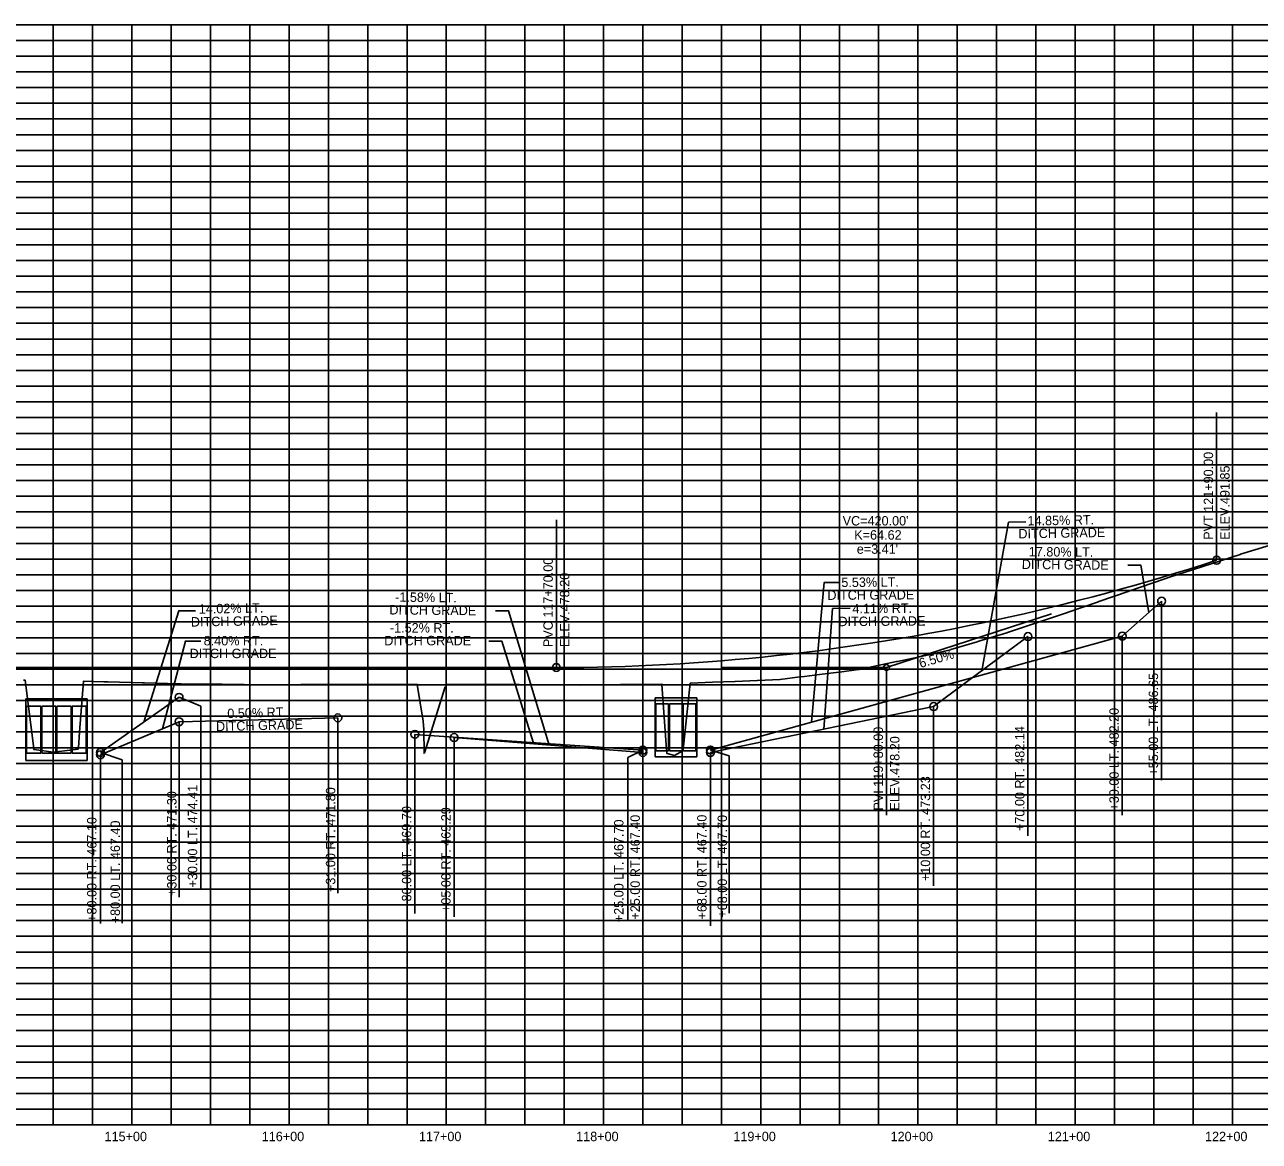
# Model space of a CAD drawing. Extents: x 1054002 to 1056762, y 395173 to 397393.
# Drawn here: x 1055464 to 1056249, y 396673 to 397383 of the extents above; entities that cross this region are included whole.
import ezdxf

# ---------------------------------------------------------------- set-up
doc = ezdxf.new("R2010")
doc.units = 0
for name, color, linetype in [('Level 8', 7, 'Continuous'), ('R_Axis_Annotation', 7, 'Continuous'), ('R_Drainage', 7, 'Continuous'), ('R_Exist Surface', 7, 'Continuous'), ('R_Grid', 7, 'Continuous'), ('R_Grid_Minor', 7, 'Continuous'), ('R_Vert Alg', 7, 'Continuous'), ('R_Vert Alg Annot', 7, 'Continuous')]:
    doc.layers.add(name, color=color, linetype=linetype)

msp = doc.modelspace()

# ---------------------------------------------------------------- linework, layer by layer
at = {"layer": 'Level 8'}
msp.add_line((1055912.29, 396918.32), (1055900.3, 396921.92), dxfattribs=at)
at = {"layer": 'R_Drainage'}
for p, q in [((1055464.75, 396954.45), (1055503.83, 396954.45)), ((1055464.75, 396954.45), (1055464.75, 396915.28)), ((1055503.83, 396954.45), (1055503.83, 396915.28)), ((1055865.04, 396955.06), (1055891.54, 396955.06)), ((1055865.04, 396955.06), (1055865.04, 396917.56)), ((1055891.54, 396955.06), (1055891.54, 396917.56)), ((1055465.29, 396949.86), (1055465.29, 396919.86)), ((1055465.29, 396949.86), (1055474.29, 396949.86)), ((1055474.29, 396949.86), (1055474.29, 396919.86)), ((1055474.96, 396949.86), (1055474.96, 396919.86)), ((1055474.96, 396949.86), (1055483.96, 396949.86)), ((1055483.96, 396949.86), (1055483.96, 396919.86)), ((1055484.63, 396949.86), (1055484.63, 396919.86)), ((1055484.63, 396949.86), (1055493.63, 396949.86)), ((1055493.63, 396949.86), (1055493.63, 396919.86)), ((1055494.29, 396949.86), (1055494.29, 396919.86)), ((1055494.29, 396949.86), (1055503.29, 396949.86)), ((1055503.29, 396949.86), (1055503.29, 396919.86)), ((1055865.63, 396951.31), (1055865.63, 396921.31)), ((1055865.63, 396951.31), (1055873.63, 396951.31)), ((1055873.63, 396951.31), (1055873.63, 396921.31)), ((1055874.29, 396951.31), (1055874.29, 396921.31)), ((1055874.29, 396951.31), (1055882.29, 396951.31)), ((1055882.29, 396951.31), (1055882.29, 396921.31)), ((1055882.96, 396951.31), (1055882.96, 396921.31)), ((1055882.96, 396951.31), (1055890.96, 396951.31)), ((1055890.96, 396951.31), (1055890.96, 396921.31)), ((1055865.63, 396921.31), (1055873.63, 396921.31)), ((1055874.29, 396921.31), (1055882.29, 396921.31)), ((1055882.96, 396921.31), (1055890.96, 396921.31)), ((1055464.75, 396915.28), (1055503.83, 396915.28)), ((1055465.29, 396919.86), (1055474.29, 396919.86)), ((1055474.96, 396919.86), (1055483.96, 396919.86)), ((1055483.96, 396919.86), (1055484.63, 396919.86)), ((1055484.63, 396919.86), (1055493.63, 396919.86)), ((1055494.29, 396919.86), (1055503.29, 396919.86)), ((1055865.04, 396917.56), (1055891.54, 396917.56))]:
    msp.add_line(p, q, dxfattribs=at)
at = {"layer": 'R_Exist Surface'}
msp.add_lwpolyline([(1055463.37, 396966.38), (1055464.37, 396966.39), (1055469.93, 396922.98), (1055469.96, 396922.21), (1055470.12, 396922.22), (1055482.15, 396920.53), (1055482.33, 396920.5), (1055492.8, 396921.8), (1055498.03, 396922.41), (1055498.22, 396922.5), (1055498.32, 396923.55), (1055499.05, 396933.35), (1055501.45, 396965.66), (1055514.54, 396965.34), (1055515.84, 396965.29), (1055517.1, 396965.23), (1055539.07, 396964.7), (1055540.3, 396964.64), (1055562.31, 396964.11), (1055563.53, 396964.06), (1055575.9, 396963.93), (1055577.44, 396963.91), (1055589.82, 396963.78), (1055602.32, 396963.66), (1055603.66, 396963.64), (1055616.17, 396963.51), (1055639.65, 396963.57), (1055640.75, 396963.58), (1055664.42, 396963.64), (1055665.34, 396963.65), (1055688.18, 396963.66), (1055689.59, 396963.65), (1055711.98, 396963.66), (1055713.85, 396963.66), (1055717.47, 396940.23), (1055718.08, 396934.95), (1055718.17, 396919.92), (1055718.37, 396920.16), (1055731.64, 396962.03), (1055732.16, 396961.95), (1055732.26, 396963.75), (1055748.33, 396963.7), (1055748.98, 396963.7), (1055765.31, 396963.65), (1055765.65, 396963.65), (1055778.3, 396963.55), (1055778.72, 396963.55), (1055791.37, 396963.45), (1055804.07, 396963.35), (1055804.41, 396963.35), (1055817.1, 396963.25), (1055830.05, 396963.4), (1055830.19, 396963.4), (1055843.15, 396963.56), (1055843.29, 396963.56), (1055856.25, 396963.71), (1055856.38, 396963.71), (1055869.36, 396963.87), (1055869.47, 396963.87), (1055872.45, 396922.07), (1055872.52, 396919.78), (1055872.7, 396919.78), (1055877.36, 396918.43), (1055877.46, 396918.47), (1055882.74, 396921.44), (1055882.76, 396921.5), (1055882.85, 396922.36), (1055887.4, 396964.42), (1055887.53, 396964.43), (1055901.71, 396965.03), (1055915.82, 396965.62), (1055916.03, 396965.63), (1055930.11, 396966.23), (1055930.35, 396966.24), (1055944.41, 396966.83), (1055944.69, 396966.85), (1055957.09, 396968.41), (1055957.17, 396968.42), (1055960.04, 396968.79), (1055969.57, 396969.97), (1055969.71, 396969.99), (1055982.02, 396971.52), (1055982.33, 396971.57), (1055994.48, 396973.08), (1055994.97, 396973.16), (1056018.69, 396978.19), (1056019.33, 396978.33), (1056043.33, 396983.42), (1056043.69, 396983.5), (1056052.92, 396985.77), (1056052.96, 396985.78), (1056053.16, 396985.84), (1056069.91, 396990.86), (1056070.94, 396991.17), (1056070.95, 396991.17), (1056088.92, 396996.54), (1056089.17, 396996.62), (1056108.4, 397003.09), (1056127.47, 397009.5), (1056127.89, 397009.63), (1056146.54, 397016.1), (1056146.94, 397016.23), (1056147.33, 397016.37), (1056165.99, 397022.84), (1056166.51, 397023.01), (1056189.37, 397030.87), (1056191.58, 397031.59), (1056213.45, 397038.67), (1056237.15, 397046.33), (1056237.54, 397046.46), (1056246.6, 397049.21), (1056260.64, 397053.44)], dxfattribs=at)
at = {"layer": 'R_Grid'}
for p, q in [((1054032.29, 397383.41), (1056732.29, 397383.41)), ((1054032.29, 397383.41), (1056732.29, 397383.41)), ((1055532.29, 396683.41), (1055532.29, 397383.41)), ((1055632.29, 396683.41), (1055632.29, 397383.41)), ((1055732.29, 396683.41), (1055732.29, 397383.41)), ((1055832.29, 396683.41), (1055832.29, 397383.41)), ((1055932.29, 396683.41), (1055932.29, 397383.41)), ((1056032.29, 396683.41), (1056032.29, 397383.41)), ((1056132.29, 396683.41), (1056132.29, 397383.41)), ((1056232.29, 396683.41), (1056232.29, 397383.41)), ((1054032.29, 397333.41), (1056732.29, 397333.41)), ((1054032.29, 397283.41), (1056732.29, 397283.41)), ((1054032.29, 397233.41), (1056732.29, 397233.41)), ((1054032.29, 397183.41), (1056732.29, 397183.41)), ((1054032.29, 397133.41), (1056732.29, 397133.41)), ((1054032.29, 397083.41), (1056732.29, 397083.41)), ((1054032.29, 397033.41), (1056732.29, 397033.41)), ((1054032.29, 396983.41), (1056732.29, 396983.41)), ((1054032.29, 396933.41), (1056732.29, 396933.41)), ((1054032.29, 396883.41), (1056732.29, 396883.41)), ((1054032.29, 396833.41), (1056732.29, 396833.41)), ((1054032.29, 396783.41), (1056732.29, 396783.41)), ((1054032.29, 396733.41), (1056732.29, 396733.41)), ((1054032.29, 396683.41), (1056732.29, 396683.41))]:
    msp.add_line(p, q, dxfattribs=at)
at = {"layer": 'R_Grid_Minor'}
for p, q in [((1055482.29, 396683.41), (1055482.29, 397383.41)), ((1055507.29, 396683.41), (1055507.29, 397383.41)), ((1055557.29, 396683.41), (1055557.29, 397383.41)), ((1055582.29, 396683.41), (1055582.29, 397383.41)), ((1055607.29, 396683.41), (1055607.29, 397383.41)), ((1055657.29, 396683.41), (1055657.29, 397383.41)), ((1055682.29, 396683.41), (1055682.29, 397383.41)), ((1055707.29, 396683.41), (1055707.29, 397383.41)), ((1055757.29, 396683.41), (1055757.29, 397383.41)), ((1055782.29, 396683.41), (1055782.29, 397383.41)), ((1055807.29, 396683.41), (1055807.29, 397383.41)), ((1055857.29, 396683.41), (1055857.29, 397383.41)), ((1055882.29, 396683.41), (1055882.29, 397383.41)), ((1055907.29, 396683.41), (1055907.29, 397383.41)), ((1055957.29, 396683.41), (1055957.29, 397383.41)), ((1055982.29, 396683.41), (1055982.29, 397383.41)), ((1056007.29, 396683.41), (1056007.29, 397383.41)), ((1056057.29, 396683.41), (1056057.29, 397383.41)), ((1056082.29, 396683.41), (1056082.29, 397383.41)), ((1056107.29, 396683.41), (1056107.29, 397383.41)), ((1056157.29, 396683.41), (1056157.29, 397383.41)), ((1056182.29, 396683.41), (1056182.29, 397383.41)), ((1056207.29, 396683.41), (1056207.29, 397383.41)), ((1054032.29, 397373.41), (1056732.29, 397373.41)), ((1054032.29, 397363.41), (1056732.29, 397363.41)), ((1054032.29, 397353.41), (1056732.29, 397353.41)), ((1054032.29, 397343.41), (1056732.29, 397343.41)), ((1054032.29, 397323.41), (1056732.29, 397323.41)), ((1054032.29, 397313.41), (1056732.29, 397313.41)), ((1054032.29, 397303.41), (1056732.29, 397303.41)), ((1054032.29, 397293.41), (1056732.29, 397293.41)), ((1054032.29, 397273.41), (1056732.29, 397273.41)), ((1054032.29, 397263.41), (1056732.29, 397263.41)), ((1054032.29, 397253.41), (1056732.29, 397253.41)), ((1054032.29, 397243.41), (1056732.29, 397243.41)), ((1054032.29, 397223.41), (1056732.29, 397223.41)), ((1054032.29, 397213.41), (1056732.29, 397213.41)), ((1054032.29, 397203.41), (1056732.29, 397203.41)), ((1054032.29, 397193.41), (1056732.29, 397193.41)), ((1054032.29, 397173.41), (1056732.29, 397173.41)), ((1054032.29, 397163.41), (1056732.29, 397163.41)), ((1054032.29, 397153.41), (1056732.29, 397153.41)), ((1054032.29, 397143.41), (1056732.29, 397143.41)), ((1054032.29, 397123.41), (1056732.29, 397123.41)), ((1054032.29, 397113.41), (1056732.29, 397113.41)), ((1054032.29, 397103.41), (1056732.29, 397103.41)), ((1054032.29, 397093.41), (1056732.29, 397093.41)), ((1054032.29, 397073.41), (1056732.29, 397073.41)), ((1054032.29, 397063.41), (1056732.29, 397063.41)), ((1054032.29, 397053.41), (1056732.29, 397053.41)), ((1054032.29, 397043.41), (1056732.29, 397043.41)), ((1054032.29, 397023.41), (1056732.29, 397023.41)), ((1054032.29, 397013.41), (1056732.29, 397013.41)), ((1054032.29, 397003.41), (1056732.29, 397003.41)), ((1054032.29, 396993.41), (1056732.29, 396993.41)), ((1054032.29, 396973.41), (1056732.29, 396973.41)), ((1054032.29, 396963.41), (1056732.29, 396963.41)), ((1054032.29, 396953.41), (1056732.29, 396953.41)), ((1054032.29, 396943.41), (1056732.29, 396943.41)), ((1054032.29, 396923.41), (1056732.29, 396923.41)), ((1054032.29, 396913.41), (1056732.29, 396913.41)), ((1054032.29, 396903.41), (1056732.29, 396903.41)), ((1054032.29, 396893.41), (1056732.29, 396893.41)), ((1054032.29, 396873.41), (1056732.29, 396873.41)), ((1054032.29, 396863.41), (1056732.29, 396863.41)), ((1054032.29, 396853.41), (1056732.29, 396853.41)), ((1054032.29, 396843.41), (1056732.29, 396843.41)), ((1054032.29, 396823.41), (1056732.29, 396823.41)), ((1054032.29, 396813.41), (1056732.29, 396813.41)), ((1054032.29, 396803.41), (1056732.29, 396803.41)), ((1054032.29, 396793.41), (1056732.29, 396793.41)), ((1054032.29, 396773.41), (1056732.29, 396773.41)), ((1054032.29, 396763.41), (1056732.29, 396763.41)), ((1054032.29, 396753.41), (1056732.29, 396753.41)), ((1054032.29, 396743.41), (1056732.29, 396743.41)), ((1054032.29, 396723.41), (1056732.29, 396723.41)), ((1054032.29, 396713.41), (1056732.29, 396713.41)), ((1054032.29, 396703.41), (1056732.29, 396703.41)), ((1054032.29, 396693.41), (1056732.29, 396693.41))]:
    msp.add_line(p, q, dxfattribs=at)
at = {"layer": 'R_Vert Alg'}
for p, q in [((1056162.29, 396994.41), (1056187.29, 397016.66)), ((1055900.3, 396921.92), (1056162.29, 396994.41)), ((1056042.29, 396949.56), (1056102.29, 396994.11)), ((1055107.29, 396974.41), (1055802.29, 396974.41)), ((1055512.31, 396920.42), (1055562.29, 396955.46)), ((1055900.29, 396920.41), (1056042.29, 396949.56)), ((1055512.29, 396918.91), (1055562.29, 396939.91)), ((1055562.29, 396939.91), (1055663.29, 396942.41)), ((1055712.29, 396931.9), (1055857.29, 396921.91)), ((1055737.29, 396929.86), (1055857.29, 396920.41))]:
    msp.add_line(p, q, dxfattribs=at)
msp.add_lwpolyline([(1055802.29, 396974.41), (1055811.04, 396974.44), (1055819.79, 396974.53), (1055828.54, 396974.68), (1055837.29, 396974.89), (1055846.04, 396975.15), (1055854.79, 396975.48), (1055863.54, 396975.86), (1055872.29, 396976.31), (1055881.04, 396976.81), (1055889.79, 396977.38), (1055898.54, 396978), (1055907.29, 396978.68), (1055916.04, 396979.42), (1055924.79, 396980.22), (1055933.54, 396981.08), (1055942.29, 396982), (1055951.04, 396982.97), (1055959.79, 396984.01), (1055968.54, 396985.11), (1055977.29, 396986.26), (1055986.04, 396987.48), (1055994.79, 396988.75), (1056003.54, 396990.08), (1056021.04, 396992.93), (1056029.79, 396994.44), (1056038.54, 396996.01), (1056047.29, 396997.64), (1056056.04, 396999.33), (1056064.79, 397001.07), (1056073.54, 397002.88), (1056082.29, 397004.75), (1056091.04, 397006.67), (1056099.79, 397008.66), (1056108.54, 397010.7), (1056117.29, 397012.8), (1056126.04, 397014.97), (1056134.79, 397017.19), (1056143.54, 397019.47), (1056152.29, 397021.81), (1056161.04, 397024.21), (1056169.79, 397026.67), (1056178.54, 397029.18), (1056187.29, 397031.76), (1056196.04, 397034.4), (1056204.79, 397037.09), (1056213.54, 397039.85), (1056222.29, 397042.66)], dxfattribs=at)
at = {"layer": 'R_Vert Alg Annot'}
for p, q in [((1056222.29, 397052.66), (1056222.29, 397136.66)), ((1055802.29, 396984.41), (1055802.29, 397068.41)), ((1056222.29, 397042.66), (1056222.29, 397052.66)), ((1056187.29, 397016.66), (1056187.29, 396986.66)), ((1056012.29, 396974.41), (1056117.29, 397008.54)), ((1056102.29, 396994.11), (1056102.29, 396951.41)), ((1056162.29, 396994.41), (1056162.29, 396964.41)), ((1055802.29, 396974.41), (1055802.29, 396984.41)), ((1056187.29, 396986.66), (1056187.29, 396902.66)), ((1055907.29, 396974.41), (1056012.29, 396974.41)), ((1056012.29, 396974.41), (1056012.29, 396964.41)), ((1056012.29, 396964.41), (1056012.29, 396880.41)), ((1056162.29, 396964.41), (1056162.29, 396880.41)), ((1055576.14, 396949.93), (1055562.29, 396955.46)), ((1055576.14, 396949.93), (1055576.14, 396925.4)), ((1056042.29, 396949.56), (1056042.29, 396919.56)), ((1056042.29, 396949.56), (1056042.29, 396919.56)), ((1056102.29, 396951.41), (1056102.29, 396867.41)), ((1055562.29, 396939.91), (1055562.29, 396828.31)), ((1055663.29, 396942.41), (1055663.29, 396830.81)), ((1055712.29, 396931.9), (1055712.29, 396901.9)), ((1055737.29, 396929.86), (1055737.29, 396899.86)), ((1055526.02, 396915.59), (1055512.31, 396920.42)), ((1055576.14, 396925.4), (1055576.14, 396833.41)), ((1055847.81, 396917.19), (1055857.29, 396921.91)), ((1055857.29, 396920.41), (1055857.29, 396812.86)), ((1055900.29, 396920.41), (1055900.29, 396810)), ((1055512.29, 396918.91), (1055512.29, 396811.54)), ((1055526.02, 396915.59), (1055526.02, 396889.11)), ((1055847.81, 396917.19), (1055847.81, 396890.71)), ((1055912.29, 396918.32), (1055912.29, 396895.43)), ((1056042.29, 396919.56), (1056042.29, 396835.56)), ((1056042.29, 396919.56), (1056042.29, 396835.56)), ((1055712.29, 396901.9), (1055712.29, 396817.9)), ((1055737.29, 396899.86), (1055737.29, 396815.86)), ((1055526.02, 396889.11), (1055526.02, 396811.86)), ((1055847.81, 396890.71), (1055847.81, 396813.47)), ((1055912.29, 396895.43), (1055912.29, 396818.19))]:
    msp.add_line(p, q, dxfattribs=at)
for points in [[(1056101.02, 397067.12), (1056089.91, 397066.87), (1056072.83, 396972.24)], [(1056165.77, 397039.51), (1056174.14, 397039.51), (1056179.08, 397009.36)], [(1055982.17, 397028.57), (1055972.7, 397028.57), (1055964.66, 396939.73)], [(1055572.73, 397010.58), (1055562.09, 397010.56), (1055539.82, 396939.71)], [(1055763.5, 397010.58), (1055771.88, 397010.58), (1055797.73, 396925.1)], [(1055989.14, 397012.16), (1055978.03, 397011.91), (1055972.46, 396935.23)], [(1055576.17, 396991.29), (1055566.36, 396991.24), (1055551.78, 396935.5)], [(1055759.44, 396991.29), (1055767.51, 396991.29), (1055787.64, 396926.85)]]:
    msp.add_lwpolyline(points, dxfattribs=at)
for centre, radius in [((1056222.29, 397042.66), 2.5), ((1056187.29, 397016.66), 2.5), ((1056102.29, 396994.11), 2.5), ((1056162.29, 396994.41), 2.5), ((1055802.29, 396974.41), 2.5), ((1056012.29, 396974.41), 1.85), ((1055562.29, 396955.46), 2.5), ((1056042.29, 396949.56), 2.5), ((1056042.29, 396949.56), 2.5), ((1055663.29, 396942.41), 2.5), ((1055562.29, 396939.91), 2.5), ((1055712.29, 396931.9), 2.5), ((1055737.29, 396929.86), 2.5), ((1055512.29, 396918.91), 2.5), ((1055512.31, 396920.42), 2.5), ((1055857.29, 396921.91), 2.5), ((1055857.29, 396920.41), 2.5), ((1055900.29, 396920.41), 2.5), ((1055900.3, 396921.92), 2.5)]:
    msp.add_circle(centre, radius, dxfattribs=at)

# ---------------------------------------------------------------- texts
at = {"layer": 'R_Axis_Annotation'}
for s, p in [('115+00', (1055514.89, 396673.06)), ('116+00', (1055614.89, 396673.06)), ('117+00', (1055714.89, 396673.06)), ('118+00', (1055814.89, 396673.06)), ('119+00', (1055914.89, 396673.06)), ('120+00', (1056014.89, 396673.06)), ('121+00', (1056114.89, 396673.06)), ('122+00', (1056214.89, 396673.06))]:
    msp.add_text(s, height=6, dxfattribs=at).set_placement(p)
at = {"layer": 'R_Vert Alg Annot'}
for s, rotation, p in [('PVT 121+90.00', 90, (1056220.04, 397055.66)), ('ELEV.491.85', 90, (1056230.54, 397055.66)), ('14.85% RT.', 0.93721, (1056102.03, 397064.75)), ('  DITCH GRADE', 0.93721, (1056091.78, 397056.46)), ('17.80% LT.', 359.45838, (1056102.78, 397045.19)), ('PVC 117+70.00', 90, (1055800.04, 396987.41)), ('DITCH GRADE', 359.45838, (1056098.33, 397037.1)), ('ELEV.478.20', 90, (1055810.54, 396987.41)), ('5.53% LT.', 0.29718, (1055983.58, 397025.63)), ('  DITCH GRADE', 0.29718, (1055970.24, 397017.43)), ('14.02% LT.', 1.00707, (1055574.89, 397008.67)), (' -1.58% LT.', 359.45838, (1055697.51, 397016.29)), ('4.11% RT.', 0.46245, (1055990.64, 397008.9)), (' DITCH GRADE', 1.00707, (1055567.65, 397000.41)), ('DITCH GRADE', 359.45838, (1055696.06, 397008.17)), ('  DITCH GRADE', 0.46245, (1055977.32, 397000.66)), (' -1.52% RT.', 0.02212, (1055694.19, 396996.66)), ('8.40% RT.', 360, (1055577.95, 396988.5)), ('DITCH GRADE', 0.02212, (1055692.82, 396988.53)), ('  DITCH GRADE', 360, (1055564.57, 396980.38)), ('6.50%', 16.19885, (1056033.92, 396974.07)), ('+55.00 LT. 486.65', 90, (1056185.04, 396905.66)), ('0.50% RT.', 1.4321, (1055593.06, 396942.2)), ('+30.00 LT. 482.20', 90, (1056160.04, 396883.41)), ('DITCH GRADE', 1.4321, (1055585.88, 396933.89)), ('PVI 119+80.00', 90, (1056010.04, 396883.41)), ('+70.00 RT. 482.14', 90, (1056100.04, 396870.41)), ('ELEV.478.20', 90, (1056020.54, 396883.41)), ('+10.00 RT. 473.23', 90, (1056040.04, 396838.56)), ('+10.00 RT. 473.23', 90, (1056040.04, 396838.56)), ('+30.00 LT. 474.41', 90, (1055573.87, 396834.45)), ('+31.00 RT. 471.80', 90, (1055661.67, 396831.57)), ('+30.00 RT. 471.30', 90, (1055560.67, 396829.07)), ('+80.00 LT. 469.70', 90, (1055710.04, 396820.9)), ('+05.00 RT. 469.29', 90, (1055735.04, 396818.86)), ('+80.00 RT. 467.10', 90, (1055509.77, 396812.59)), ('+80.00 LT. 467.40', 90, (1055524.7, 396811.7)), ('+25.00 LT. 467.70', 90, (1055845, 396812.39)), ('+25.00 RT. 467.40', 90, (1055855.39, 396814.04)), ('+68.00 RT. 467.40', 90, (1055897.84, 396814.12)), ('+68.00 LT. 467.70', 90, (1055910.84, 396815.28))]:
    msp.add_text(s, height=6, rotation=rotation, dxfattribs=at).set_placement(p)
for s, p in [("VC=420.00'", (1055984.39, 397064.78)), ('K=64.62', (1055991.8, 397055.78)), ("e=3.41'", (1055993.39, 397046.78))]:
    msp.add_text(s, height=6, dxfattribs=at).set_placement(p)

doc.saveas('drawing.dxf')
